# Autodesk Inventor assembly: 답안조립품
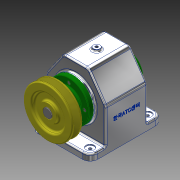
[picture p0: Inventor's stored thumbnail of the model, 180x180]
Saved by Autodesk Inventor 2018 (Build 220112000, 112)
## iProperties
Created: 2022-12
Part Number: 답안조립품
Material: 일반
Document SubType Name: Assembly
Designer: 강의실04
Author: 강의실04
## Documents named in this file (15)
- C:\Users\kimgi\Desktop\721206V1002\답안조립품.iam
- C:\Users\kimgi\Desktop\721206V1002\본체.ipt
- C:\Users\kimgi\Desktop\721206V1002\V-벨트풀리.ipt
- C:\Users\kimgi\Desktop\721206V1002\뒤커버.ipt
- C:\Users\kimgi\Desktop\721206V1002\멈춤나사 - M4x10.ipt
- C:\Users\kimgi\Desktop\721206V1002\베어링 6203.ipt
- C:\Users\kimgi\Desktop\721206V1002\볼트 M3 x 8.ipt
- C:\Users\kimgi\Desktop\721206V1002\볼트 M3 x 10.ipt
- C:\Users\kimgi\Desktop\721206V1002\스퍼기어.ipt
- C:\Users\kimgi\Desktop\721206V1002\앞커버.ipt
- C:\Users\kimgi\Desktop\721206V1002\오일 실 17 x 32 x 8.ipt
- C:\Users\kimgi\Desktop\721206V1002\축.ipt
- C:\Users\kimgi\Desktop\721206V1002\칼라.ipt
- C:\Users\kimgi\Desktop\721206V1002\키 - 5 x 5 x 18.ipt
- C:\Users\kimgi\Desktop\721206V1002\키 - 6 x 6 x 22.ipt
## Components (9 placed, 3 different names)
1. V-벨트풀리:1
2. ISO 4762 M3 x 8:1 — 각도:1
3. ISO 4762 M3 x 8:2
4. ISO 4762 M3 x 8:3
5. ISO 4762 M3 x 8:4
6. ISO 4762 M3 x 10:1 — 각도:2
7. ISO 4762 M3 x 10:2
8. ISO 4762 M3 x 10:3
9. ISO 4762 M3 x 10:4
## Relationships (2: Angle 2)
- 각도:1 [Angle]: ISO 4762 M3 x 8:1
- 각도:2 [Angle]: ISO 4762 M3 x 10:1
